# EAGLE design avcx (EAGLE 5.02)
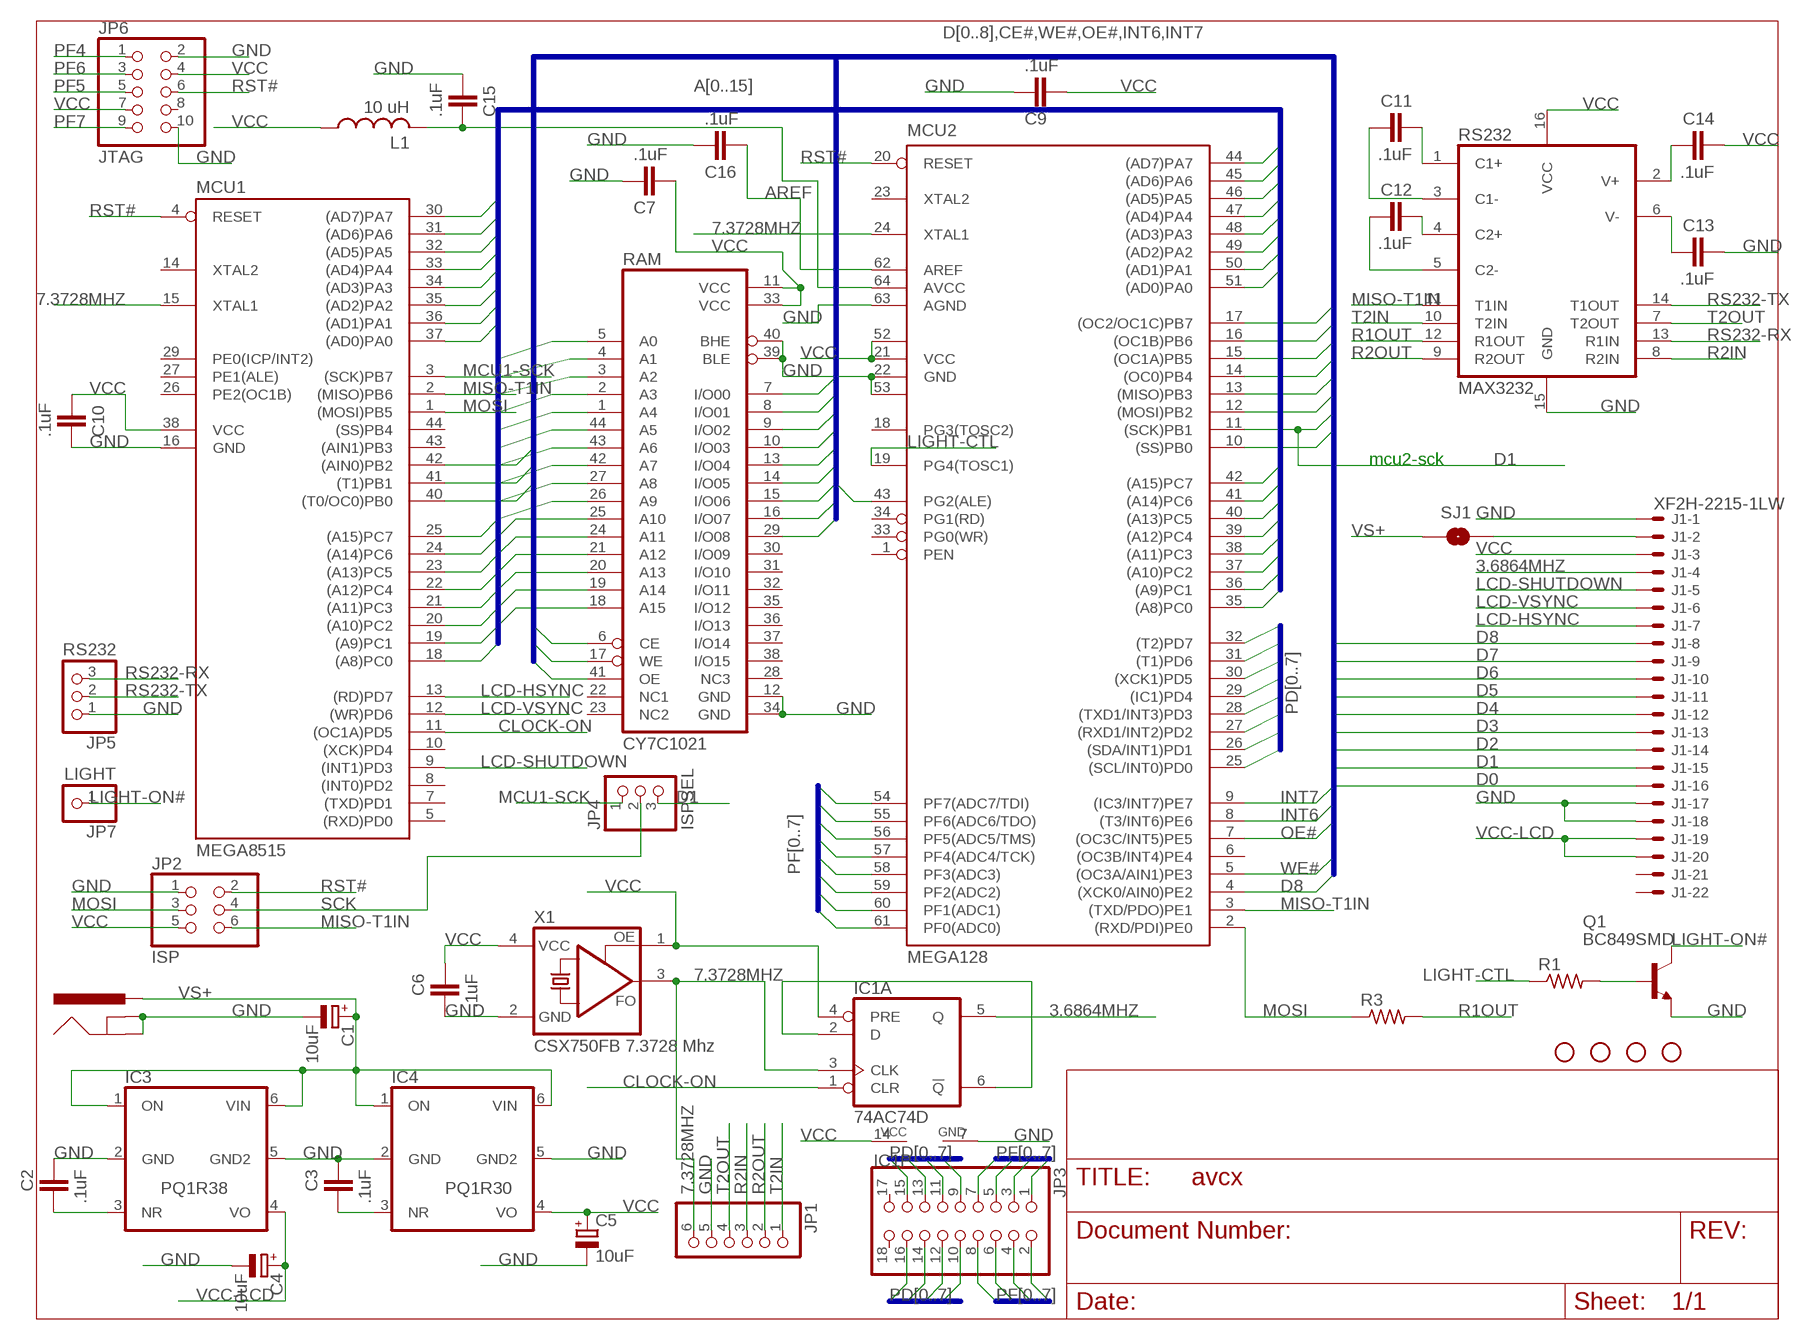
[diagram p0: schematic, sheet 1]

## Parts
C1  10uF  CPOL-EUCT3528  [CT3528]
C2  .1uF  C-EUC0603  [C0603]
C3  .1uF  C-EUC0603  [C0603]
C4  10uF  CPOL-EUCT3528  [CT3528]
C5  10uF  CPOL-EUCT3528  [CT3528]
C6  .1uF  C-EUC0603  [C0603]
C7  .1uF  C-EUC0603  [C0603]
C9  .1uF  C-EUC0603  [C0603]
C10  .1uF  C-EUC0603  [C0603]
C11  .1uF  C-EUC0603  [C0603]
C12  .1uF  C-EUC0603  [C0603]
C13  .1uF  C-EUC0603  [C0603]
C14  .1uF  C-EUC0603  [C0603]
C15  .1uF  C-EUC0603  [C0603]
C16  .1uF  C-EUC0603  [C0603]
IC1  74AC74D  [SO14]
IC3  PQ1R38  PQ1R  [SOT23-6L]
IC4  PQ1R30  PQ1R  [SOT23-6L]
J1  XF2H-2215-1LW  [XF2H-2215-1LW]
J2  POWER_JACKPTH  [POWER_JACK_PTH]
JP1  PINHD-1X6  [1X06]
JP2  ISP  PINHD-2X3  [2X03]
JP3  PINHD-2X9  [2X09]
JP4  ISPSEL  PINHD-1X3  [1X03]
JP5  RS232  PINHD-1X3  [1X03]
JP6  JTAG  PINHD-2X5  [2X05]
JP7  LIGHT  PINHD-1X1  [1X01]
L1  10 uH  L-USL2012C  [L2012C]
MCU1  MEGA8515  MEGA8515-A  [TQFP44]
MCU2  MEGA128  MEGA128-A  [TQFP64]
Q1  BC849SMD  [SOT23-BEC]
R1  R-US_R0603  [R0603]
R3  R-US_R0603  [R0603]
RAM  CY7C1021  CY7C1021CV33  [TSOPII-44]
RS232  MAX3232  MAX232SOIC16  [SO016]
SJ1  SOLDERJUMPERNO  [SJ-NO]
U$1  STAND-OFF  [STAND-OFF]
U$2  STAND-OFF  [STAND-OFF]
U$3  STAND-OFF  [STAND-OFF]
U$4  STAND-OFF  [STAND-OFF]
X1  CSX750FB 7.3728 Mhz  CSX750  [ASF]

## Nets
3.6864MHZ: IC1.5(A:Q) J1.4
7.3728MHZ: IC1.3(A:CLK) JP1.6 MCU1.15(XTAL1) MCU2.24(XTAL1) X1.3(FO)
A0: MCU1.37((AD0)PA0) MCU2.51((AD0)PA0) RAM.5(A0)
A1: MCU1.36((AD1)PA1) MCU2.50((AD1)PA1) RAM.4(A1)
A2: MCU1.35((AD2)PA2) MCU2.49((AD2)PA2) RAM.3(A2)
A3: MCU1.34((AD3)PA3) MCU2.48((AD3)PA3) RAM.2(A3)
A4: MCU1.33((AD4)PA4) MCU2.47((AD4)PA4) RAM.1(A4)
A5: MCU1.32((AD5)PA5) MCU2.46((AD5)PA5) RAM.44(A5)
A6: MCU1.31((AD6)PA6) MCU2.45((AD6)PA6) RAM.43(A6)
A7: MCU1.30((AD7)PA7) MCU2.44((AD7)PA7) RAM.42(A7)
A8: MCU1.18((A8)PC0) MCU2.35((A8)PC0) RAM.27(A8)
A9: MCU1.19((A9)PC1) MCU2.36((A9)PC1) RAM.26(A9)
A10: MCU1.20((A10)PC2) MCU2.37((A10)PC2) RAM.25(A10)
A11: MCU1.21((A11)PC3) MCU2.38((A11)PC3) RAM.24(A11)
A12: MCU1.22((A12)PC4) MCU2.39((A12)PC4) RAM.21(A12)
A13: MCU1.23((A13)PC5) MCU2.40((A13)PC5) RAM.20(A13)
A14: MCU1.24((A14)PC6) MCU2.41((A14)PC6) RAM.19(A14)
A15: MCU1.25((A15)PC7) MCU2.42((A15)PC7) RAM.18(A15)
AREF: C16.1 MCU2.62(AREF)
AVCC: C15.2 L1.2 MCU2.64(AVCC)
CE#: MCU2.43(PG2(ALE)) RAM.6(CE)
CLOCK-ON: IC1.1(A:CLR) MCU1.11((OC1A)PD5)
D0: J1.16 MCU2.10((SS)PB0) RAM.7(I/O00)
D1: J1.15 JP4.3 MCU2.11((SCK)PB1) RAM.8(I/O01)
D2: J1.14 MCU2.12((MOSI)PB2) RAM.9(I/O02)
D3: J1.13 MCU2.13((MISO)PB3) RAM.10(I/O03)
D4: J1.12 MCU2.14((OC0)PB4) RAM.13(I/O04)
D5: J1.11 MCU2.15((OC1A)PB5) RAM.14(I/O05)
D6: J1.10 MCU2.16((OC1B)PB6) RAM.15(I/O06)
D7: J1.9 MCU2.17((OC2/OC1C)PB7) RAM.16(I/O07)
D8: J1.8 MCU2.4((XCK0/AIN0)PE2) RAM.29(I/O08)
GND: C1.- C2.2 C3.2 C4.- C5.- C6.1 C7.2 C9.2 C10.2 C13.2 C15.1 C16.2 IC1.7(P:GND) IC3.2(GND) IC3.5(GND2) IC4.2(GND) IC4.5(GND2) J1.1 J1.17 J1.18 J2.GND J2.GNDBREAK JP1.5 JP2.1 JP5.1 JP6.2 JP6.10 MCU1.16(GND) MCU2.22(GND) MCU2.53(GND1) MCU2.63(AGND) Q1.E RAM.12(GND) RAM.34(GND) RAM.39(BLE) RAM.40(BHE) RS232.15(GND) X1.2(GND)
INT6: MCU1.42((AIN0)PB2) MCU2.8((T3/INT6)PE6)
INT7: MCU1.41((T1)PB1) MCU2.9((IC3/INT7)PE7)
LCD-HSYNC: J1.7 MCU1.13((RD)PD7)
LCD-SHUTDOWN: J1.5 MCU1.9((INT1)PD3)
LCD-VSYNC: J1.6 MCU1.12((WR)PD6)
LIGHT-CTL: MCU2.19(PG4(TOSC1)) R1.1
LIGHT-ON#: JP7.1 Q1.C
MCU1-SCK: JP4.1 MCU1.3((SCK)PB7)
MISO-T1IN: JP2.6 MCU1.2((MISO)PB6) MCU2.3((TXD/PDO)PE1) RS232.11(T1IN)
MOSI: JP2.3 MCU1.1((MOSI)PB5) MCU2.2((RXD/PDI)PE0) R3.1
N$1: C11.2 RS232.1(C1+)
N$2: C11.1 RS232.3(C1-)
N$3: C14.1 RS232.2(V+)
N$4: C12.2 RS232.4(C2+)
N$5: C12.1 RS232.5(C2-)
N$6: C13.1 RS232.6(V-)
N$7: IC1.2(A:D) IC1.6(A:!Q)
N$8: Q1.B R1.2
N$9: J1.2 SJ1.2
N$13: C2.1 IC3.3(NR)
N$14: C3.1 IC4.3(NR)
OE#: MCU1.40((T0/OC0)PB0) MCU2.7((OC3C/INT5)PE5) RAM.41(OE)
PD0: JP3.15 MCU2.25((SCL/INT0)PD0)
PD1: JP3.16 MCU2.26((SDA/INT1)PD1)
PD2: JP3.13 MCU2.27((RXD1/INT2)PD2)
PD3: JP3.14 MCU2.28((TXD1/INT3)PD3)
PD4: JP3.11 MCU2.29((IC1)PD4)
PD5: JP3.12 MCU2.30((XCK1)PD5)
PD6: JP3.9 MCU2.31((T1)PD6)
PD7: JP3.10 MCU2.32((T2)PD7)
PF0: JP3.2 MCU2.61(PF0(ADC0))
PF1: JP3.1 MCU2.60(PF1(ADC1))
PF2: JP3.4 MCU2.59(PF2(ADC2))
PF3: JP3.3 MCU2.58(PF3(ADC3))
PF4: JP3.6 JP6.1 MCU2.57(PF4(ADC4/TCK))
PF5: JP3.5 JP6.5 MCU2.56(PF5(ADC5/TMS))
PF6: JP3.8 JP6.3 MCU2.55(PF6(ADC6/TDO))
PF7: JP3.7 JP6.9 MCU2.54(PF7(ADC7/TDI))
R1OUT: R3.2 RS232.12(R1OUT)
R2IN: JP1.3 RS232.8(R2IN)
R2OUT: JP1.2 RS232.9(R2OUT)
RS232-RX: JP5.3 RS232.13(R1IN)
RS232-TX: JP5.2 RS232.14(T1OUT)
RST#: JP2.2 JP6.6 MCU1.4(RESET) MCU2.20(RESET)
SCK: JP2.4 JP4.2
T2IN: JP1.1 RS232.10(T2IN)
T2OUT: JP1.4 RS232.7(T2OUT)
VCC: C5.+ C6.2 C7.1 C9.1 C10.1 C14.2 IC1.4(A:PRE) IC1.14(P:VCC) IC4.4(VO) J1.3 JP2.5 JP6.4 JP6.7 L1.1 MCU1.38(VCC) MCU2.21(VCC) MCU2.52(VCC1) RAM.11(VCC) RAM.33(VCC) RS232.16(VCC) X1.1(OE) X1.4(VCC)
VCC-LCD: C4.+ IC3.4(VO) J1.19 J1.20
VS+: C1.+ IC3.1(ON) IC3.6(VIN) IC4.1(ON) IC4.6(VIN) J2.PWR SJ1.1
WE#: MCU2.5((OC3A/AIN1)PE3) RAM.17(WE)
Unconnected: IC1.8(B:!Q) IC1.9(B:Q) IC1.10(B:PRE) IC1.11(B:CLK) IC1.12(B:D) IC1.13(B:CLR) J1.21 J1.22 JP3.17 JP3.18 JP6.8 MCU1.5((RXD)PD0) MCU1.6(NC1) MCU1.7((TXD)PD1) MCU1.8((INT0)PD2) MCU1.10((XCK)PD4) MCU1.14(XTAL2) MCU1.17(NC2) MCU1.26(PE2(OC1B)) MCU1.27(PE1(ALE)) MCU1.28(NC3) MCU1.29(PE0(ICP/INT2)) MCU1.39(NC4) MCU1.43((AIN1)PB3) MCU1.44((SS)PB4) MCU2.1(PEN) MCU2.6((OC3B/INT4)PE4) MCU2.18(PG3(TOSC2)) MCU2.23(XTAL2) MCU2.33(PG0(WR)) MCU2.34(PG1(RD)) RAM.22(NC1) RAM.23(NC2) RAM.28(NC3) RAM.30(I/O09) RAM.31(I/O10) RAM.32(I/O11) RAM.35(I/O12) RAM.36(I/O13) RAM.37(I/O14) RAM.38(I/O15)

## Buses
A[0..15]
D[0..8],CE#,WE#,OE#,INT6,INT7
PD[0..7]
PF[0..7]

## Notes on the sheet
- mcu2-sck

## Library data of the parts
C1 C4 C5 = rcl:CPOL-EU: POLARIZED CAPACITOR, European symbol
C2 C3 C6 C7 C9-C16 = resistor:C-EU: CAPACITOR, European symbol
IC1 = 74xx-eu:74*74: Dual D type positive edge triggered FLIP FLOP, preset and clear
IC3 IC4 = Jdr-Eagle:PQ1R: Sharp Low Power Loss Low Voltage Regulator
J1 = con-omron:XF2*-22?: OMRON FPC Connector Source : http://www.omron.com/ecb/products/pdf/fpc.pdf
J2 = SparkFun:POWER_JACK: Power Jack This is the standard 5.5mm barrel jack for power. The PTH is the most common, proven, reliable, footprint. All others are experimental. The Slot footprint only works if the mill layer is transmitted to the PCB fab house so be warned. Spark Fun Electronics SKU : PRT-00119. Mating wall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
JP1 = pinhead:PINHD-1X6: PIN HEADER
JP2 = pinhead:PINHD-2X3: PIN HEADER
JP3 = pinhead:PINHD-2X9: PIN HEADER
JP4 JP5 = pinhead:PINHD-1X3: PIN HEADER
JP6 = pinhead:PINHD-2X5: PIN HEADER
JP7 = pinhead:PINHD-1X1: PIN HEADER
L1 = rcl:L-US: INDUCTOR, American symbol
MCU1 = atmel:MEGA8515: MICROCONTROLLER 8 Kbytes FLASH 512 bytes SRAM 512 bytes EEPROM USART 8-channel 10 bit ADC Source: avr.lbr
MCU2 = atmel:MEGA128: MICROCONTROLLER 128 Kbytes FLASH 4 Kbytes SRAM 4 Kbytes EEPROM DUAL USART 8-channel 10 bit ADC Source: avr.lbr
Q1 = transistor-npn:BC849*: NPN Transistor
R1 R3 = resistor:R-US_: RESISTOR, American symbol
RAM = Jdr-Eagle:CY7C1021CV33
RS232 = SparkFun:MAX232: RS232 Transceiver Very common IC. This is generically called 'MAX232', but works with the 3V equivalent MAX3232 generic ICs. Field tested and mother approved. Spark Fun Electronics SKU : COM-00316 (DIP) and COM-00589 (SMD)
SJ1 = SparkFun:SOLDERJUMPER: Solder Jumper
U$1-U$4 = SparkFun:STAND-OFF: Stand Off
X1 = Jdr-Eagle:CSX750

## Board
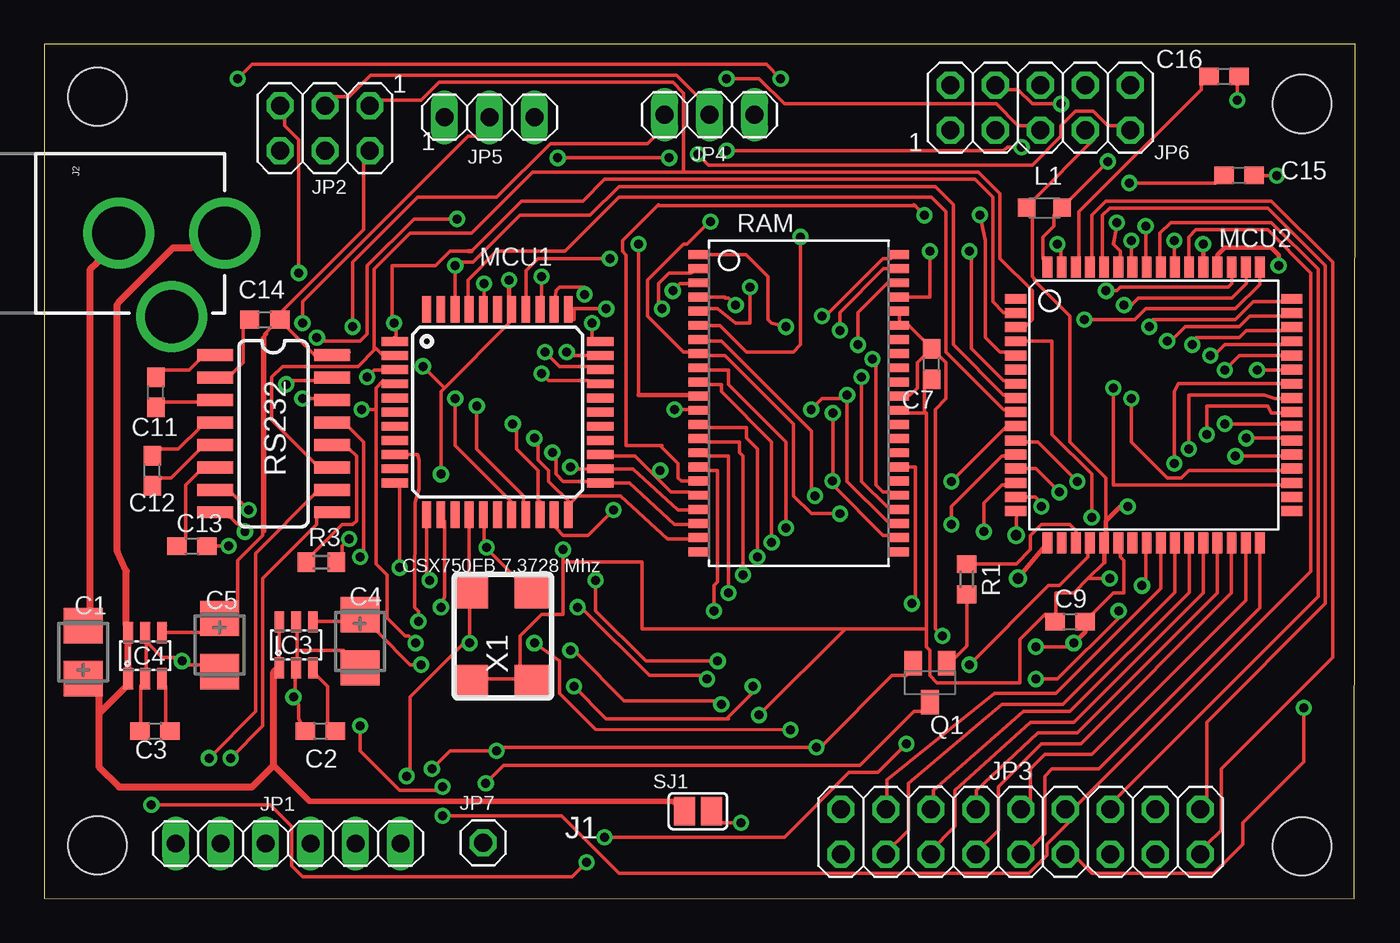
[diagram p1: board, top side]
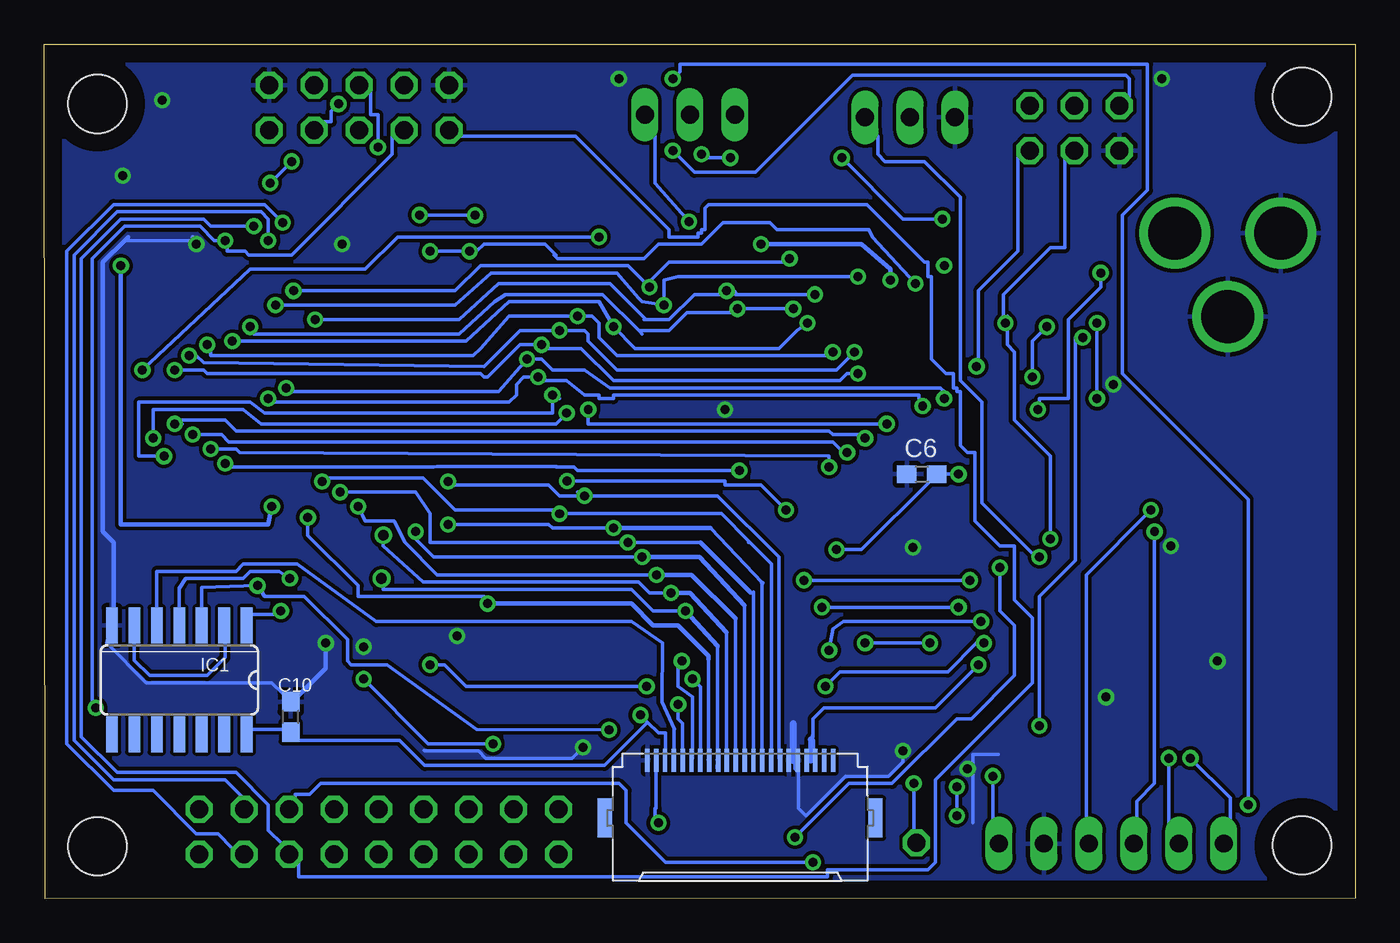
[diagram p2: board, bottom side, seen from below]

Size 74.09 x 48.3 mm. Coordinates in mm from the lower left corner, seen from the top.
Outline: 0,0.03 74.04,0 74.09,48.3 0,48.3 0,0.03
Copper layers (1*16): Top 0.035mm / dielectric 1.5mm / Bottom 0.035mm
Design rules "default *": minimum track width 8mil, minimum drill 20mil, track to track 8mil, track to pad 8mil, pad to pad 8mil, via to via 8mil, smd to smd 8mil, copper to edge 40mil, drill to drill 8mil, minimum pad ring 10mil, minimum via ring 8mil, stop-mask expansion 4mil, vias tented up to drill 0mil, thermal gap 10mil

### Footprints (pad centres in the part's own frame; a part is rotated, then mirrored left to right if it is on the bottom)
CT3528 = smd 2 x 2.2: + -1.5,0; - 1.5,0
C0603 = smd 1.1 x 1: 1 -0.85,0; 2 0.85,0
SO14 = smd 0.66 x 2.032: 1 -3.81,-3.073; 2 -2.54,-3.073; 3 -1.27,-3.073; 4 0,-3.073; 5 1.27,-3.073; 6 2.54,-3.073; 7 3.81,-3.073; 8 3.81,3.073; 9 2.54,3.073; 10 1.27,3.073; 11 0,3.073; 12 -1.27,3.073; 13 -2.54,3.073; 14 -3.81,3.073
SOT23-6L = smd 0.55 x 1.2: 1 -0.9,-1.3; 2 0.05,-1.3; 3 1,-1.3; 4 1,1.3; 5 0.05,1.3; 6 -0.9,1.3
XF2H-2215-1LW = smd 1.3 x 0.25: 1 3.175,5.25; 2 3.175,4.75; 3 3.175,4.25; 4 3.175,3.75; 5 3.175,3.25; 6 3.175,2.75; 7 3.175,2.25; 8 3.175,1.75; 9 3.175,1.25; 10 3.175,0.75; 11 3.175,0.25; 12 3.175,-0.25; 13 3.175,-0.75; 14 3.175,-1.25; 15 3.175,-1.75; 16 3.175,-2.25; 17 3.175,-2.75; 18 3.175,-3.25; 19 3.175,-3.75; 20 3.175,-4.25; 21 3.175,-4.75; 22 3.175,-5.25 | smd 2.2 x 0.8: M1 -0.075,7.65; M2 -0.075,-7.65
POWER_JACK_PTH = drill 2.997 round: GND 0,7.7; GNDBREAK 4.7,10.7; PWR 0,13.7
1X06 = drill 1.016 long: 1 -6.35,0; 2 -3.81,0; 3 -1.27,0; 4 1.27,0; 5 3.81,0; 6 6.35,0
2X03 = drill 1.016 octagon: 1 -2.54,-1.27; 2 -2.54,1.27; 3 0,-1.27; 4 0,1.27; 5 2.54,-1.27; 6 2.54,1.27
2X09 = drill 1.016 octagon: 1 -10.16,-1.27; 2 -10.16,1.27; 3 -7.62,-1.27; 4 -7.62,1.27; 5 -5.08,-1.27; 6 -5.08,1.27; 7 -2.54,-1.27; 8 -2.54,1.27; 9 0,-1.27; 10 0,1.27; 11 2.54,-1.27; 12 2.54,1.27; 13 5.08,-1.27; 14 5.08,1.27; 15 7.62,-1.27; 16 7.62,1.27; 17 10.16,-1.27; 18 10.16,1.27
1X03 = drill 1.016 long: 1 -2.54,0; 2 0,0; 3 2.54,0
2X05 = drill 1.016 octagon: 1 -5.08,-1.27; 2 -5.08,1.27; 3 -2.54,-1.27; 4 -2.54,1.27; 5 0,-1.27; 6 0,1.27; 7 2.54,-1.27; 8 2.54,1.27; 9 5.08,-1.27; 10 5.08,1.27
1X01 = drill 1.016 octagon: 1 0,0
L2012C = smd 1 x 1: 1 -1,0; 2 1,0
TQFP44 = smd 1.5 x 0.5: 1 -5.8,4; 2 -5.8,3.2; 3 -5.8,2.4; 4 -5.8,1.6; 5 -5.8,0.8; 6 -5.8,0; 7 -5.8,-0.8; 8 -5.8,-1.6; 9 -5.8,-2.4; 10 -5.8,-3.2; 11 -5.8,-4; 23 5.8,-4; 24 5.8,-3.2; 25 5.8,-2.4; 26 5.8,-1.6; 27 5.8,-0.8; 28 5.8,0; 29 5.8,0.8; 30 5.8,1.6; 31 5.8,2.4; 32 5.8,3.2; 33 5.8,4 | smd 0.5 x 1.5: 12 -4,-5.8; 13 -3.2,-5.8; 14 -2.4,-5.8; 15 -1.6,-5.8; 16 -0.8,-5.8; 17 0,-5.8; 18 0.8,-5.8; 19 1.6,-5.8; 20 2.4,-5.8; 21 3.2,-5.8; 22 4,-5.8; 34 4,5.8; 35 3.2,5.8; 36 2.4,5.8; 37 1.6,5.8; 38 0.8,5.8; 39 0,5.8; 40 -0.8,5.8; 41 -1.6,5.8; 42 -2.4,5.8; 43 -3.2,5.8; 44 -4,5.8
TQFP64 = smd 1.194 x 0.559: 1 -7.8,6; 2 -7.8,5.2; 3 -7.8,4.4; 4 -7.8,3.6; 5 -7.8,2.8; 6 -7.8,2; 7 -7.8,1.2; 8 -7.8,0.4; 9 -7.8,-0.4; 10 -7.8,-1.2; 11 -7.8,-2; 12 -7.8,-2.8; 13 -7.8,-3.6; 14 -7.8,-4.4; 15 -7.8,-5.2; 16 -7.8,-6; 33 7.8,-6; 34 7.8,-5.2; 35 7.8,-4.4; 36 7.8,-3.6; 37 7.8,-2.8; 38 7.8,-2; 39 7.8,-1.2; 40 7.8,-0.4; 41 7.8,0.4; 42 7.8,1.2; 43 7.8,2; 44 7.8,2.8; 45 7.8,3.6; 46 7.8,4.4; 47 7.8,5.2; 48 7.8,6 | smd 0.559 x 1.194: 17 -6,-7.8; 18 -5.2,-7.8; 19 -4.4,-7.8; 20 -3.6,-7.8; 21 -2.8,-7.8; 22 -2,-7.8; 23 -1.2,-7.8; 24 -0.4,-7.8; 25 0.4,-7.8; 26 1.2,-7.8; 27 2,-7.8; 28 2.8,-7.8; 29 3.6,-7.8; 30 4.4,-7.8; 31 5.2,-7.8; 32 6,-7.8; 49 6,7.8; 50 5.2,7.8; 51 4.4,7.8; 52 3.6,7.8; 53 2.8,7.8; 54 2,7.8; 55 1.2,7.8; 56 0.4,7.8; 57 -0.4,7.8; 58 -1.2,7.8; 59 -2,7.8; 60 -2.8,7.8; 61 -3.6,7.8; 62 -4.4,7.8; 63 -5.2,7.8; 64 -6,7.8
SOT23-BEC = smd 1 x 1.4: B -0.95,-1.1; C 0,1.1; E 0.95,-1.1
R0603 = smd 1 x 1.1: 1 -0.85,0; 2 0.85,0
TSOPII-44 = smd 0.5 x 1.2: 1 -8.4,-5.627; 2 -7.6,-5.627; 3 -6.8,-5.627; 4 -6,-5.627; 5 -5.2,-5.627; 6 -4.4,-5.627; 7 -3.6,-5.627; 8 -2.8,-5.627; 9 -2,-5.627; 10 -1.2,-5.627; 11 -0.4,-5.627; 12 0.4,-5.627; 13 1.2,-5.627; 14 2,-5.627; 15 2.8,-5.627; 16 3.6,-5.627; 17 4.4,-5.627; 18 5.2,-5.627; 19 6,-5.627; 20 6.8,-5.627; 21 7.6,-5.627; 22 8.4,-5.627; 23 8.4,5.627; 24 7.6,5.627; 25 6.8,5.627; 26 6,5.627; 27 5.2,5.627; 28 4.4,5.627; 29 3.6,5.627; 30 2.8,5.627; 31 2,5.627; 32 1.2,5.627; 33 0.4,5.627; 34 -0.4,5.627; 35 -1.2,5.627; 36 -2,5.627; 37 -2.8,5.627; 38 -3.6,5.627; 39 -4.4,5.627; 40 -5.2,5.627; 41 -6,5.627; 42 -6.8,5.627; 43 -7.6,5.627; 44 -8.4,5.627
SO016 = smd 0.66 x 2.032: 1 -4.445,-3.315; 2 -3.175,-3.315; 3 -1.905,-3.315; 4 -0.635,-3.315; 5 0.635,-3.315; 6 1.905,-3.315; 7 3.175,-3.315; 8 4.445,-3.315; 9 4.445,3.315; 10 3.175,3.315; 11 1.905,3.315; 12 0.635,3.315; 13 -0.635,3.315; 14 -1.905,3.315; 15 -3.175,3.315; 16 -4.445,3.315
SJ-NO = smd 1.168 x 1.6: 1 -0.762,0; 2 0.762,0
STAND-OFF = hole 3.302: 0,0
ASF = smd 1.8 x 2: 1 1.21,1.34; 2 6.21,1.34; 3 6.21,4.84; 4 1.21,4.84

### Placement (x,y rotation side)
C1  2.2,13.94 90 top
C2  15.61,9.47 180 top
C3  6.26,9.47 180 top
C4  17.84,14.55 270 top
C5  9.92,14.35 270 top
C6  24.5,24 0 bottom
C7  50.15,30.22 90 top
C9  57.98,15.67 0 top
C10  60.16,10.28 90 bottom
C11  6.31,28.62 90 top
C12  6.11,24.2 90 top
C13  8.34,19.93 0 top
C14  12.46,32.74 0 top
C15  67.53,40.89 180 top
C16  66.69,46.48 0 top
IC1  66.46,12.36 180 bottom
IC3  14.19,14.35 0 top
IC4  5.65,13.74 0 top
J1  34.76,4.64 90 bottom
J2  -3.49,37.61 270 top
JP1  13.78,3.12 0 top
JP2  15.86,43.56 0 top
JP3  55.18,3.78 180 top
JP4  37.6,44.32 0 top
JP5  25.16,44.17 0 top
JP6  56.3,44.72 0 top
JP7  24.8,3.17 0 top
L1  56.53,39.06 0 top
MCU1  25.62,27.5 0 top
MCU2  62.7,27.91 0 top
Q1  50.05,12.21 180 top
R1  52.13,18.05 270 top
R3  15.66,19.02 180 top
RAM  42.63,28.01 270 top
RS232  12.97,26.28 270 top
SJ1  36.94,4.95 0 top
U$1  3.01,3.02 0 top
U$2  71.08,2.97 0 top
U$3  3.01,45.33 0 top
U$4  71.08,44.93 0 top
X1  28.92,11.09 90 top

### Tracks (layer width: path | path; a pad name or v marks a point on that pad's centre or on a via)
3.6864MHZ
  Bottom 0.203: J1.4 38.51,9.57 | 38.51,9.57 38.51,9.61 | IC1.5 67.73,18.51 63.26,18.51 62.85,18.92 59.8,18.92 55.33,15.67 40.91,15.67 39.15,14.45 39.18,11.12 38.47,9.57 38.51,9.57
7.3728MHZ  (via drill 0.51)
  Top 0.203: MCU1.15 24.02,17.11 24.04,17.09 | v27.7,14.45 29.12,13.43 29.12,11.6 31.15,9.57 v42.18,9.55 | 24.04,17.09 24.08,17.13 X1.3 | 24.04,17.09 v24.04,14.45 23.74,14.45 20.69,11.4 20.69,7.34 v20.48,6.93 | MCU2.24 62.27,20.11 62.24,20.14 62.24,17.9 v62.04,17.7
  Bottom 0.203: v42.18,9.55 49.64,9.57 54.72,13.23 56.76,13.23 56.96,13.43 56.96,14.65 59.4,17.09 61.63,17.09 v62.04,17.7 65.19,17.6 IC1.3 | v24.04,14.45 v27.7,14.45 | v20.48,6.93 20.48,4.49 JP1.6
A0  (via drill 0.51)
  Top 0.203: MCU2.51 67.12,34.77 66.92,34.56 60.82,34.56 60.62,34.36 v60.01,34.36 | 37.05,33.35 38.06,33.35 39.08,32.53 39.89,32.53 v39.89,34.56 | MCU1.37 27.22,35.5 27.9,36.19 v31.97,36.19
  Top 0.229: 37.05,33.35 RAM.5
  Bottom 0.203: v60.01,34.36 50.86,34.36 49.44,35.78 41.11,35.78 v39.89,34.56 39.79,34.97 38.77,35.99 32.27,35.99 v31.97,36.19
A1  (via drill 0.51)
  Top 0.203: MCU2.50 67.93,34.77 67.12,33.96 61.84,33.96 61.43,33.55 v61.02,33.55 | MCU1.36 28.11,33.39 v28.11,35.17 | RAM.4 38.47,34.01 38.47,33.96 38.67,33.96 v39.08,33.55
  Bottom 0.203: v61.02,33.55 50.86,33.55 48.83,35.38 41.72,35.38 40.5,33.96 40.3,33.75 v39.08,33.55 39.08,34.97 38.27,35.17 v28.11,35.17
A2  (via drill 0.51)
  Top 0.203: MCU2.49 68.7,34.72 67.32,33.35 62.24,33.35 61.63,32.74 v58.79,32.74 | MCU1.35 28.92,34.36 29.12,34.56 30.54,34.56 v30.54,34.16 | v35.52,34.36 35.93,34.77 36.54,34.77 RAM.3
  Bottom 0.203: 40.15,32.79 40.09,32.74 | 40.15,32.79 42.13,34.77 48.43,34.77 50.66,32.74 v58.79,32.74 | v30.54,34.16 34.91,34.16 | 34.91,34.16 35.01,34.16 | 34.91,34.16 35.12,34.36 v35.52,34.36 35.93,34.16 37.35,34.16 38.77,32.74 40.2,32.74 40.15,32.79
A3  (via drill 0.51)
  Top 0.203: MCU1.34 29.53,32.74 29.93,32.74 29.93,33.35 v31.76,33.35 | MCU2.48 69.96,33.75 68.34,33.75 67.32,32.74 62.65,32.74 v62.45,32.33 | v34.91,33.35 34.71,33.55 34.71,34.77 35.32,35.38 36.54,35.38 RAM.2
  Bottom 0.203: v62.45,32.33 62.24,31.92 50.66,31.92 48.63,33.75 48.02,34.16 42.53,34.16 40.45,32.08 | 40.45,32.08 40.3,31.92 | 31.76,32.94 v31.76,33.35 v34.91,33.35 35.32,33.14 37.76,33.14 38.77,32.13 40.4,32.13 40.45,32.08
A4  (via drill 0.51)
  Top 0.203: RAM.1 39.67,36.41 40.91,35.17 40.91,32.74 41.11,32.53 v41.92,32.33 | 70.17,33.14 70.2,33.11 MCU2.47 69.96,32.94 68.14,32.94 67.53,32.33 64.48,32.33 63.87,31.72 v63.46,31.52 | MCU1.33 30.96,31.5 30.95,31.52 v30.95,32.53
  Bottom 0.203: v63.46,31.52 50.25,31.52 47.82,33.75 42.74,33.75 v41.92,32.33 40.7,31.11 32.58,31.11 31.56,32.13 v30.95,32.53
A5  (via drill 0.51)
  Top 0.203: 70.37,32.33 70.39,32.31 MCU2.46 69.96,32.13 67.93,32.13 67.53,31.72 65.09,31.72 v64.88,31.31 | v29.53,30.91 29.73,30.7 30.95,30.7 | 30.95,30.7 | 30.95,30.7 MCU1.32 | RAM.44 47.82,36.19 47.41,36.19 44.36,33.14 v43.96,32.94
  Bottom 0.203: v64.88,31.31 64.68,31.11 64.68,30.7 49.85,30.7 49.44,31.11 47.82,32.94 v43.96,32.94 43.14,32.94 42.74,32.53 42.74,31.72 41.72,30.7 29.73,30.7 v29.53,30.91
A6  (via drill 0.51)
  Top 0.203: RAM.43 47.44,35.61 44.97,33.14 v44.97,32.13 | 70.37,31.52 70.38,31.51 MCU2.45 69.96,31.31 66.71,31.31 66.31,30.91 v65.9,30.7 | 31.36,29.89 31.37,29.9 MCU1.31 30.75,30.09 29.12,30.09 v28.31,30.91
  Bottom 0.203: v65.9,30.7 65.49,30.7 65.09,30.3 49.24,30.09 47.21,32.13 v44.97,32.13 43.55,32.13 43.35,31.92 43.35,31.52 41.72,29.89 29.32,29.89 v28.31,30.91
A7  (via drill 0.51)
  Top 0.203: v66.71,29.89 67.53,30.7 69.96,30.7 MCU2.44 | v45.99,31.31 45.99,33.14 47.82,34.97 RAM.42 | v28.11,29.69 28.51,29.28 30.75,29.28 MCU1.30
  Bottom 0.203: v66.71,29.89 65.09,29.89 64.88,29.69 49.44,29.69 49.24,29.48 49.04,29.48 47.21,31.31 v45.99,31.31 45.58,31.11 43.75,31.11 41.92,29.28 29.12,29.28 28.71,29.69 v28.11,29.69
A8  (via drill 0.51)
  Top 0.203: 47,30.3 v46.8,30.5 47,30.09 47,23.39 47.41,22.98 47.82,22.98 RAM.27 | v23.23,28.27 23.23,25.62 26.48,22.37 MCU1.18 | v60.41,28.88 60.41,23.39 69.96,23.39 MCU2.35
  Bottom 0.203: v23.23,28.27 23.23,28.67 23.43,28.88 42.13,28.88 43.55,29.89 45.38,29.89 45.99,30.5 v46.8,30.5 48.43,28.67 60.21,28.67 v60.41,28.88
A9  (via drill 0.51)
  Top 0.203: 48.26,21.97 RAM.26 47.82,22.17 47.61,22.17 46.19,23.59 v46.19,29.48 | v24.45,27.86 24.45,25.42 27.09,22.78 27.09,22.37 MCU1.19 | v61.43,28.27 61.43,25.83 63.46,23.8 64.28,23.8 64.68,24.2 69.96,24.2 MCU2.36
  Bottom 0.203: v24.45,27.86 24.65,28.27 24.65,28.47 41.92,28.47 41.92,28.27 42.74,28.27 42.74,28.47 43.55,28.47 44.56,29.28 45.78,29.28 v46.19,29.48 47,29.48 47.41,29.08 47.41,28.47 47.82,28.06 61.23,28.06 v61.43,28.27
A10  (via drill 0.51)
  Top 0.203: 28.02,22.46 MCU1.20 27.9,22.37 27.9,24.2 26.68,25.42 26.68,26.44 v26.48,26.84 | RAM.25 47.82,21.36 47.61,21.36 45.38,23.59 v45.38,28.47 44.97,28.27 43.96,28.27 v43.35,27.66 | v67.32,25.01 69.96,25.01 MCU2.37
  Bottom 0.203: 44.97,28.27 v45.38,28.47 45.38,27.45 61.63,27.45 62.45,28.06 68.75,28.06 68.75,25.01 v67.32,25.01 | v43.35,27.66 43.35,26.84 v26.48,26.84
A11  (via drill 0.51)
  Top 0.203: v32.17,21.97 30.75,20.54 29.32,20.54 28.92,20.95 28.92,21.15 MCU1.21 | RAM.24 47.82,20.54 47.41,20.54 44.56,23.39 v44.54,23.62 44.56,24 v44.56,27.45 | v67.93,26.03 69.96,26.03 MCU2.38
  Bottom 0.203: v44.56,27.45 45.17,26.84 61.84,26.84 62.85,27.66 67.93,27.66 v67.93,26.03 | v32.17,21.97 33.59,23.39 35.62,23.39 35.62,23.62 v44.54,23.62
A12  (via drill 0.51)
  Top 0.203: 70.43,26.64 MCU2.39 69.96,26.84 v66.71,26.84 | RAM.21 36.94,20.34 35.22,20.34 32.58,22.78 30.14,22.78 29.73,22.37 | 29.73,22.37 28.51,23.59 28.51,24.2 27.9,24.81 27.9,25.62 v27.7,26.03 | MCU1.22 29.73,22.37
  Bottom 0.203: v27.7,26.03 28.11,26.23 29.53,26.23 29.73,26.44 63.26,26.44 63.87,27.05 66.31,27.05 v66.71,26.84 66.31,26.84
A13  (via drill 0.51)
  Top 0.203: MCU2.40 70.44,27.45 69.36,27.45 69.15,27.86 65.7,27.86 v65.7,26.23 | RAM.20 37.01,21.19 37.05,21.15 35.62,21.15 33.07,23.5 MCU1.23 30.75,23.59 29.32,23.59 28.92,24 28.92,24.81 v28.71,25.22
  Bottom 0.203: v28.71,25.22 29.12,25.42 29.53,25.83 63.67,25.83 64.07,26.23 v65.7,26.23
A14  (via drill 0.51)
  Top 0.203: v64.68,25.42 64.68,28.47 68.95,28.47 69.56,28.27 70.46,28.27 MCU2.41 | v29.73,24.4 29.83,24.3 MCU1.24 33.29,24.3 35.83,21.97 36.84,21.97 36.89,22.01 RAM.19
  Top 0.254: v64.68,25.42 64.68,25.67
  Bottom 0.203: v29.73,24.4 29.73,25.01 63.06,25.22 63.26,25.42 v64.68,25.42
A15  (via drill 0.51)
  Top 0.203: MCU2.42 64.1,29.11 63.87,28.67 v63.87,24.61 | 34.4,24 33.39,25.01 31.97,25.01 MCU1.25 | 34.4,24 35.42,22.98 36.44,22.98 RAM.18 | 34.4,24 34.61,24 v34.81,24.2
  Bottom 0.203: 45.17,24.43 45.15,24.43 | 45.17,24.43 51.88,24.43 52.08,24.4 63.46,24.4 v63.87,24.61 | v34.81,24.2 43.96,24.2 44.16,24.4 45.17,24.4 45.17,24.43
AREF
  Top 0.203: C16.1 65.39,46.15 65.39,45.74 58.48,38.83 58.48,36.19 MCU2.62
AVCC  (via drill 0.51)
  Top 0.203: 56.76,36.19 MCU2.64 56.45,36.19 56.45,37.41 57.06,38.02 57.06,38.63 L1.2 57.87,39.44 v60.11,41.68 | v61.33,40.46 66.2,40.46 C15.2
  Bottom 0.203: v60.11,41.68 v61.33,40.46
CE#  (via drill 0.51)
  Top 0.203: RAM.6 38.18,32.41 39.69,30.91 42.33,30.91 42.74,31.31 v42.74,37.41 | MCU2.43 70.39,29.91 70.37,29.89 v68.54,29.89
  Bottom 0.203: v42.74,37.41 54.12,37.41 55.94,35.58 62.45,35.58 v68.54,29.89
CLOCK-ON  (via drill 0.51)
  Top 0.203: v20.08,18.72 20.08,23.39 MCU1.11 | v31.66,3.48 41.82,3.48 45.48,7.13 47.1,7.13 v48.73,8.76 | v56.05,12.42 57.26,12.42 60.72,15.87 v60.72,16.28
  Bottom 0.203: v20.08,18.72 20.08,16.28 19.27,15.46 19.27,12.62 21.7,10.18 22.52,10.18 26.18,6.52 28.61,6.52 v31.66,3.48 | v48.73,8.76 52.39,8.76 v56.05,12.42 | v60.72,16.28 60.92,16.07 62.34,16.07 IC1.1
D0  (via drill 0.51)
  Top 0.203: RAM.7 37.45,31.52 38.27,31.52 43.35,26.44 43.35,23.19 v43.55,22.78 | v51.27,23.59 54.32,26.64 MCU2.10
  Bottom 0.203: v43.55,22.78 36.03,22.78 32.58,19.32 32.58,7.95 J1.16 | v43.55,22.78 43.96,22.98 | v51.27,23.59 50.86,23.39 45.58,23.39 44.97,22.78 v43.55,22.78
D1  (via drill 0.51)
  Top 0.203: v58.38,23.59 56.15,25.83 55.33,25.83 MCU2.11 | v44.97,21.76 43.35,21.76 42.33,22.78 42.33,26.84 38.47,30.7 37.45,30.7 RAM.8 36.54,30.91 36.13,30.91 34.1,32.94 34.1,34.97 36.13,37 36.34,37 37.35,38.02 v37.66,38.27
  Top 0.254: 36.79,30.81 36.8,30.81 RAM.8
  Bottom 0.203: J1.15 32.98,8.35 32.98,18.92 34.25,20.19 | 34.25,20.19 35.83,21.76 v44.97,21.76 45.38,21.97 50.86,21.97 52.69,23.8 57.98,23.8 v58.38,23.59 | 34.25,20.19 34.3,20.14 | v37.66,38.27 39.59,40.46 39.59,43.1 JP4.3
D2  (via drill 0.51)
  Top 0.203: RAM.9 37.45,29.89 38.67,29.89 38.67,29.08 41.92,25.83 v41.92,20.95 | v51.27,21.15 51.27,22.17 54.12,25.01 54.32,25.01 MCU2.12
  Bottom 0.203: 33.49,17.85 36.44,20.95 | 33.54,7.82 33.54,17.85 | v51.27,21.15 45.58,21.15 45.38,20.95 v41.92,20.95
  Bottom 0.254: 36.44,20.95 v41.92,20.95 | 33.54,17.85 33.49,17.85 | J1.14 33.54,7.82
D3  (via drill 0.51)
  Top 0.203: MCU2.13 56.04,24.31 v57.37,22.98 | RAM.10 37.45,29.08 38.27,29.08 38.27,28.67 41.11,25.83 v41.11,20.14
  Bottom 0.203: J1.13 34.01,17.29 | 34.01,17.29 34.01,17.33 | v57.37,22.98 53.1,22.98 52.29,21.76 52.29,20.14 v41.11,20.14 37,20.14 | 34.01,17.29 34.2,17.29 34.2,17.34 | 34.01,17.29 34,17.29
  Bottom 0.254: 34.2,17.34 37,20.14
D4  (via drill 0.51)
  Top 0.203: RAM.13 37.45,26.64 39.69,26.64 39.69,26.03 40.3,25.42 v40.3,19.32 | v53.1,20.75 53.1,22.37 54.12,23.39 54.32,23.39 MCU2.14
  Bottom 0.203: J1.12 34.51,16.58 | v53.1,20.75 53.1,20.34 52.08,19.32 v40.3,19.32
  Bottom 0.254: 34.51,16.58 37.05,19.32 v40.3,19.32 | J1.12
D5  (via drill 0.51)
  Top 0.203: MCU2.15 56.01,22.71 56.35,22.37 v56.35,22.17 | RAM.14 37.45,25.83 39.28,25.83 39.28,25.22 39.48,25.01 v39.48,18.31
  Bottom 0.203: v39.48,18.31 51.88,18.31 53.71,20.14 54.32,21.36 55.94,21.36 v56.35,22.17 | J1.11 35.01,15.82
  Bottom 0.229: 35.01,7.34 J1.11 | 35.04,15.84 35.01,15.87
  Bottom 0.254: 35.01,15.82 35.04,15.84 37.5,18.31 v39.48,18.31 | J1.11
D6  (via drill 0.51, 0.6 pad 0.25)
  Top 0.203: v54.93,20.54 54.93,21.97 MCU2.16 | RAM.15 37.45,25.01 38.67,25.01 v38.67,17.29
  Bottom 0.203: 35.52,7.83 35.52,15.06 | v38.67,17.29 39.89,17.29 40.5,17.9 52.69,17.9 54.93,19.93 v54.93,20.54
  Bottom 0.254: 35.52,15.06 37.61,17.29 v38.67,17.29 | J1.10 35.52,7.83
D7  (via drill 0.51, 0.6 pad 0.25)
  Top 0.203: RAM.16 37.45,24.2 38.06,24.2 38.06,17.9 37.86,17.7 v37.86,16.28
  Top 0.254: v55.03,18.11 MCU2.17
  Bottom 0.203: v37.86,16.28 39.69,16.28 40.91,17.5 54.93,17.5 54.93,17.9 v55.03,18.11 | 36.03,7.84 36.03,14.24
  Bottom 0.229: 36.03,7.34 J1.9 | 36.03,14.24 36.03,14.3
  Bottom 0.254: 36.03,14.3 v37.86,16.28 | J1.9 36.03,7.84
D8  (via drill 0.51)
  Top 0.203: MCU2.4 56.95,31.51 56.96,31.52 56.96,26.23 59.2,24 v59.2,21.56 | RAM.29 48.83,24.4 49.24,24.4 49.24,16.68 v49.04,16.68
  Bottom 0.203: 36.54,7.85 36.54,13.53 | v59.2,21.56 59.2,20.54 56.35,17.7 56.35,17.09 49.24,17.09 v49.04,16.68
  Bottom 0.254: J1.8 36.54,7.85 | 36.54,13.53 36.54,13.74 38.27,15.46 39.69,15.46 40.91,16.68 v49.04,16.68
GND  (via drill 0.51)
  Top 0.203: C9.2 59.2,16.07 60.41,17.29 61.02,17.29 61.02,19.12 60.82,19.32 60.82,19.53 MCU2.22 | X1.2 26.68,18.11 25.06,19.73 25.06,19.93 v25.01,19.86 24.85,20.34 24.85,21.15 MCU1.16 | 14.29,14.04 14.29,15.06 IC3.5 | 14.29,14.04 14.29,13.64 IC3.2 | 14.29,14.04 16.93,14.04 C4.- 17.03,12.21 | 9.61,13.43 C5.- 8.9,13.23 8.09,13.23 v7.79,13.43 7.48,13.64 6.67,13.64 5.85,14.45 IC4.5 5.75,14.45 5.75,13.03 IC4.2 5.45,12.01 5.45,9.77 C3.2 | v35.62,27.66 36.44,27.66 RAM.12 | 2.3,16.28 C1.- 2.6,16.28 | C13.2 v10.43,19.93 | v13.68,29.08 13.88,29.28 15.3,29.28 RS232.15 | C2.2 14.39,10.18 14.39,10.99 v14.08,11.4 14.19,11.81 14.19,12.62 IC3.2 | IC3.2 14.39,12.62 | v50.76,14.85 50.36,15.26 50.36,27.66 50.97,28.27 50.97,30.3 50.56,30.7 C7.2 | 48.73,28.27 RAM.34 48.73,28.47 48.93,28.47 49.34,28.88 49.34,30.3 49.75,30.7 C7.2 | 48.73,13.43 Q1.E 48.73,12.62 47.92,12.62 44.06,8.76 v43.65,8.56 | v56.05,14.24 57.87,14.24 v58.18,14.45 | v69.66,40.86 68.85,40.86 C15.1 | v67.42,45.13 67.42,46.15 C16.2 | v57.26,37 57.47,36.8 57.47,36.19 MCU2.63 | v41.62,46.35 40.81,47.16 11.75,47.16 v10.94,46.35 | v21.91,7.34 22.92,8.35 v25.57,8.35 25.97,8.56 v43.65,8.56 | v43.65,8.56 43.68,8.56 | C7.2 49.75,31.52 48.73,32.53 RAM.39 48.32,32.53 48.32,33.14 RAM.40
  Top 0.254: MCU2.53 v65.5,37 v65.49,37 | C9.2 58.83,15.09 v58.18,14.45
  Top 0.406: 2.6,16.28 2.6,35.58 3.01,35.99 J2.GND
  Bottom 0.203: C10.2 60.62,11.6 61.23,12.21 68.34,12.21 70.57,14.45 IC1.7 | 21.6,4.29 21.6,8.15 20.18,8.15 | 69.56,37.21 65.9,37.21 v65.49,37 | J1.17 31.97,8.35 | v25.57,8.35 25.57,7.74 26.38,6.93 28.82,6.93 31.05,4.69 31.46,5.1 31.46,7.13 31.66,7.34 31.66,7.82 | v43.65,8.56 44.26,7.95 49.14,7.95 49.54,8.35 52.59,8.35 52.62,8.38
  Bottom 0.254: v65.49,37 65.49,37.21 65.7,37.41 | 69.36,37.41 69.56,37.21 70.78,35.99 70.78,20.75 70.17,20.14 70.17,15.46 | IC1.7 70.19,15.44 | C10.2 60.07,11.13 58.18,13.03 v58.18,14.45 | J1.18 31.66,7.82 31.76,7.82
  Bottom 0.406: 31.76,7.82 31.76,9.9
  pour Bottom: 0.37,48.03 73.8,48.03 73.72,0.3 0.29,0.3
INT6  (via drill 0.51)
  Top 0.203: MCU1.42 23.22,35.77 v23.23,35.78 23.63,35.99 24.24,35.99 26.89,38.63 29.63,38.63 | 54.93,28.27 54.9,28.29 MCU2.8 54.42,28.47 54.22,28.47 51.37,31.31 51.37,39.24 50.36,40.25 32.47,40.25 30.85,38.63 29.63,38.63 | 29.63,38.63 29.73,38.63
  Bottom 0.203: v23.23,35.78 23.43,35.78
INT7
  Top 0.203: MCU1.41 23.94,33.96 23.94,34.97 25.57,36.6 29.43,36.6 32.47,39.64 50.15,39.64 50.97,38.83 50.97,30.91 54.22,27.66 54.42,27.66 MCU2.9
LCD-HSYNC  (via drill 0.51)
  Top 0.203: v22.42,16.48 22.62,17.09 22.62,21.36 22.42,21.56 MCU1.13 | v37.45,12.42 37.05,12.62 34.2,12.62 30.54,16.28 v30.14,16.48
  Bottom 0.203: J1.7 37.01,11.97 v37.45,12.42 | v22.42,16.48 v30.14,16.48
LCD-SHUTDOWN  (via drill 0.51)
  Top 0.203: MCU1.9 21.11,25.1 21.2,24.81 21.2,23.19 20.97,22.4 20.92,16.48 21.15,16.25 v21.15,15.67 | v38.27,10.99 37.86,11.2 32.78,11.2 30.14,13.84 v29.73,14.04
  Bottom 0.203: v29.73,14.04 29.53,15.26 28.92,15.67 v21.15,15.67 | v38.27,10.99 38.27,10.18 38.01,9.93 J1.5
LCD-VSYNC  (via drill 0.51)
  Top 0.203: v38.06,13.43 35.01,13.43 34,13.44 34,13.43 31.15,16.28 v31.15,18 | MCU1.12 21.6,21.15 21.6,18.31 v21.78,18
  Bottom 0.203: v21.78,18 v31.15,18 | J1.6 37.51,8 37.45,7.95 37.45,11.4 38.27,12.01 38.27,13.43 v38.06,13.43
LIGHT-CTL
  Top 0.203: MCU2.19 58.3,20.83 57.98,21.15 56.35,21.15 55.74,20.54 55.74,19.73 54.93,18.92 52.29,18.92 52.27,18.9 R1.1
LIGHT-ON#  (via drill 0.51)
  Top 0.203: v24.96,6.52 25.97,7.54 46.09,7.54 49.14,10.59 49.75,10.59 Q1.C
  Bottom 0.203: v24.96,6.52 24.96,3.88 JP7.1
MCU1-SCK  (via drill 0.51)
  Top 0.203: v18.25,29.48 18.66,29.89 19.27,29.89 MCU1.3 | v17.44,32.33 17.44,35.99 21.09,39.64 25.57,39.64 28.61,42.69 34.1,42.69 34.51,43.1 JP4.1
  Bottom 0.203: v18.25,29.48 18.25,31.52 v17.44,32.33
MISO-T1IN
  Top 0.203: 20.89,37.61 20.79,37.61 | MCU1.2 19.16,30.7 18.76,31.11 18.71,31.06 | 18.71,31.06 17.74,30.09 13.47,30.09 12.87,29.48 12.87,27.05 15.3,24.61 RS232.11 | 20.89,37.61 20.69,37.61 18.66,35.58 18.66,31.11 18.71,31.06 | 20.89,37.61 24.14,37.61 27.6,41.07 36.13,41.07 | MCU2.3 55.44,32.33 55.84,32.74 55.84,34.36 54.01,36.19 54.01,39.85 52.79,41.07 36.13,41.07 | 36.13,41.07 36.13,45.54 35.52,46.15 22.31,46.15 21.3,45.13 19.06,45.13 JP2.6
MOSI  (via drill 0.51)
  Top 0.203: 19.77,31.72 MCU1.1 19.88,31.72 19.88,32.13 v19.77,32.53 19.67,32.94 19.67,35.78 22.11,35.78 22.92,36.6 23.94,36.6 | v17.23,20.34 16.83,19.93 16.83,19.53 R3.1 | 24.14,36.6 26.99,39.44 30.44,39.44 31.66,40.66 52.59,40.66 53.61,39.64 53.61,33.75 54.22,33.14 54.42,33.14 MCU2.2
  Top 0.254: 23.94,36.6 24.14,36.6
  Bottom 0.203: v17.23,20.34 17.23,25.01 19.27,27.05 19.27,30.91 19.67,31.31 19.67,32.13 v19.77,32.53 | v19.77,32.53 19.67,32.94 | JP2.3 16.42,41.88 16.42,36.8 17.23,36.8 19.88,34.16 19.88,32.94 v19.77,32.53
N$1
  Top 0.203: C11.2 6.77,29.89 8.19,29.89 8.8,30.5 RS232.1
N$2
  Top 0.203: C11.1 6.77,28.06 8.8,28.06 RS232.3
N$3
  Top 0.203: C14.1 11.24,32.33 11.24,30.3 10.63,29.69 RS232.2
N$4
  Top 0.203: C12.2 6.57,25.42 7.58,25.42 8.8,26.64 RS232.4
N$5
  Top 0.203: C12.1 6.57,23.8 7.18,23.8 8.8,25.42 RS232.5
N$6
  Top 0.203: C13.1 7.99,20.34 7.99,23.39 8.8,24.2 RS232.6
N$7
  Bottom 0.203: IC1.6 69,13.48 68.14,12.62 64.88,12.62 63.87,13.64 63.87,15.46 63.89,15.44 IC1.2
N$8
  Top 0.203: Q1.B 51,13.29 51.07,13.23 52.13,14.3 R1.2
N$9  (via drill 0.51)
  Top 0.203: v39.38,4.29 38.16,4.29 SJ1.2
  Bottom 0.203: v39.38,4.29 39.59,4.69 39.59,5.1 39.51,5.1 J1.2 | J1.2
N$13
  Top 0.203: 15.2,12.62 IC3.3 15.4,12.62 16.02,12.01 16.02,9.77 C2.1
N$14
  Top 0.203: C3.1 6.87,9.77 6.87,12.01 IC4.3
OE#  (via drill 0.51)
  Top 0.203: 54.93,29.08 54.93,29.11 MCU2.7 54.42,29.28 54.22,29.28 52.39,31.11 52.39,36.19 v52.29,36.6 | RAM.41 50.05,34.01 v50.05,36.6 | MCU1.40 24.85,33.35 v24.85,34.77
  Bottom 0.203: v52.29,36.6 v50.05,36.6 49.64,36.6 49.24,37 45.78,37 45.23,36.44 | 45.23,36.44 45.17,36.39 | v24.85,34.77 27.29,37.41 27.5,37.82 32.68,37.82 33.08,38.22 35.73,38.22 36.94,37 39.38,37 40.2,36.19 45.07,36.19 45.28,36.39 45.23,36.44
PD0
  Top 0.203: MCU2.25 63.1,17.54 57.16,11.6 53.71,11.6 47.61,6.73 47.61,5.51 47.41,5.3 47.56,5.15 JP3.15
PD1
  Top 0.203: MCU2.26 63.9,17.32 57.57,10.99 54.12,10.99 48.83,6.52 48.83,3.88 47.46,2.51 | 47.46,2.51 47.41,2.46 | JP3.16 47.46,2.51
PD2
  Top 0.203: MCU2.27 64.7,17.31 57.98,10.59 55.33,10.59 50.25,6.12 50.25,4.9 JP3.13
PD3
  Top 0.203: MCU2.28 65.5,17.3 58.18,9.98 55.74,9.98 51.47,6.12 51.47,4.08 50.05,2.66 50.1,2.61 JP3.14
PD4
  Top 0.203: MCU2.29 66.3,17.29 58.38,9.37 56.15,9.37 52.69,6.12 52.69,5.1 JP3.11
PD5
  Top 0.203: MCU2.30 67.1,17.27 58.59,8.76 56.35,8.76 53.91,6.32 53.91,3.88 52.54,2.51 | 52.54,2.51 52.49,2.46 | JP3.12 52.54,2.51
PD6
  Top 0.203: MCU2.31 67.9,16.85 59.2,8.15 56.55,8.15 55.74,7.34 55.74,5.51 55.54,5.51 55.13,5.1 JP3.9
PD7
  Top 0.203: MCU2.32 68.7,16.43 59.6,7.34 56.96,7.34 56.55,6.93 56.55,3.68 55.18,2.31 | 55.18,2.31 55.13,2.26 | 55.18,2.31 JP3.10
PF0
  Top 0.203: MCU2.61 59.2,36.19 59.2,38.63 60.01,39.44 69.36,39.44 72.81,35.99 72.81,13.64 66.51,7.34 66.51,3.88 65.7,3.07 JP3.2
PF1
  Top 0.203: MCU2.60 59.8,36.19 59.8,38.63 60.21,39.04 69.15,39.04 72.4,35.78 72.4,16.68 65.7,9.98 65.7,5.71 JP3.1
PF2  (via drill 0.51)
  Top 0.203: MCU2.59 60.7,35.87 60.82,35.99 60.82,36.6 60.41,37 60.62,38.02 v60.62,38.22
  Bottom 0.203: v60.62,38.22 61.63,39.24 70.17,39.24 72.81,36.6 72.81,8.76 70.17,6.12 67.93,6.12 65.49,3.68 64.28,3.68 63.46,2.87 JP3.4
PF3  (via drill 0.51)
  Top 0.203: MCU2.58 61.43,35.78 v61.43,37.21
  Bottom 0.203: v61.43,37.21 61.43,38.43 61.84,38.83 69.96,38.83 72.4,36.39 72.4,8.96 70.17,6.73 63.87,6.73 62.85,5.71 JP3.3
PF4  (via drill 0.51)
  Top 0.203: MCU2.57 62.3,35.73 62.24,35.78 v62.24,38.02
  Bottom 0.203: v62.24,38.02 64.68,38.02 65.09,38.43 69.76,38.43 72,36.19 72,9.16 69.96,7.13 63.26,7.13 61.43,5.3 61.43,3.88 60.62,3.07 JP3.6 59.7,2.05 59.7,1.24 29.83,1.24 29.83,1.65 24.14,1.65 23.74,2.05 23.74,6.73 18.25,12.21 18.25,15.87 19.27,16.89 19.27,19.93 20.08,19.93 21.5,21.36 21.5,25.22 21.91,25.22 22.31,25.62 22.31,28.67 22.52,28.67 22.52,28.88 22.72,28.88 22.72,29.69 23.13,29.69 23.94,30.5 23.94,35.17 24.14,35.17 24.14,35.99 24.35,35.99 27.6,39.24 36.54,39.24 36.74,39.04 36.74,37.82 36.94,37.82 36.94,37.61 37.15,37.61 37.15,37.41 38.77,37.41 38.77,37.82 44.06,43.1 50.56,43.1 JP6.1
PF5  (via drill 0.51)
  Top 0.203: 63.06,35.99 63.1,35.94 MCU2.56 63.06,36.19 63.06,37.61 63.67,38.22 69.36,38.22 72,35.58 72,17.09 60.62,5.71 JP3.5 | v38.57,46.35 40.4,46.35 41.82,44.93 53.81,44.93 55.03,43.71 55.64,43.71 JP6.5 | v6.06,5.3 12.76,5.3 13.98,4.08 13.98,1.85 14.59,1.24 29.83,1.24 v30.64,2.05
  Bottom 0.203: v38.57,46.35 38.16,46.76 38.16,47.16 11.75,47.16 11.75,40.05 13.17,38.63 13.17,29.69 6.06,22.58 v6.06,5.3 | v30.64,2.05 38.98,2.05 41.21,4.29 41.21,6.12 41.62,6.52 58.48,6.52 59.09,5.91 59.91,5.91 59.91,5.71 JP3.5
PF6  (via drill 0.51)
  Top 0.203: MCU2.55 63.9,36.16 63.87,36.39 v63.87,37.21 | v71.18,10.79 71.18,7.74 67.73,4.29 67.73,3.07 66.1,1.44 59.2,1.44 58.38,2.26 JP3.8
  Bottom 0.203: v71.18,10.79 71.39,10.99 71.39,36.19 69.56,38.02 65.29,38.02 64.48,37.21 v63.87,37.21 63.77,36.8 63.77,36.6 62.75,36.6 62.55,36.39 60.11,36.39 54.42,42.08 54.42,43.1 JP6.3
PF7  (via drill 0.51)
  Top 0.203: MCU2.54 64.68,36.19 64.68,37.41 65.09,37.82 69.15,37.82 71.59,35.38 71.59,18.51 58.38,5.3 JP3.7 58.08,4.49 56.66,3.07 56.66,2.46 55.64,1.44 32.47,1.44 29.22,4.69 v22.52,4.69 | v36.94,42.08 37.55,41.47 55.84,41.47 57.47,43.1 57.47,43.71 58.28,44.52 59.3,44.52 60.11,43.71 60.72,43.71 JP6.9 | v29.02,41.88 v35.32,41.88 | v23.33,38.43 20.89,38.43 18.25,35.78 18.25,31.92 17.84,31.52 15.61,31.52 v15.4,31.72 | v17.84,9.77 17.84,8.35 20.08,6.12 22.31,6.12 v22.52,6.32
  Bottom 0.203: v36.94,42.08 36.74,41.88 v35.32,41.88 | v29.02,41.88 25.57,38.43 v23.33,38.43 | v15.4,31.72 15.81,31.72 15.81,19.12 17.84,17.09 v17.84,9.77 | v22.52,4.69 v22.52,6.32
R1OUT
  Top 0.203: R3.2 15.2,19.53 16.83,21.15 17.44,21.15 17.64,21.36 17.64,25.01 17.23,25.42 RS232.12
R2IN  (via drill 0.51)
  Top 0.203: v11.34,20.75 10.53,21.56 RS232.8
  Bottom 0.203: v11.34,20.75 11.34,6.52 12.36,5.51 12.36,4.49 JP1.3
R2OUT  (via drill 0.51)
  Top 0.203: v10.53,7.95 12.36,9.77 12.36,18.11 15.4,21.15 15.4,21.56 RS232.9
  Bottom 0.203: v10.53,7.95 10.53,4.29 JP1.2
RS232-RX  (via drill 0.51)
  Top 0.203: v17.84,19.32 18.05,19.53 18.05,25.83 17.23,26.64 RS232.13
  Bottom 0.203: v17.84,19.32 18.05,19.32 21.09,22.37 21.09,28.06 22.31,29.28 22.31,39.64 24.35,41.68 26.58,41.68 26.99,42.08 26.99,43.1 JP5.3
RS232-TX  (via drill 0.51)
  Top 0.203: v14.59,28.27 15.4,28.27 RS232.14 | v14.59,32.53 14.59,33.75 23.94,43.1 24.55,43.1 JP5.2
  Bottom 0.203: v14.59,28.27 v14.59,32.53
RST#  (via drill 0.51)
  Top 0.203: v52.29,13.23 56.76,17.7 57.37,17.7 58.99,19.32 58.99,19.53 MCU2.20 | 38.57,10.18 31.76,10.18 v29.93,12.01 | 38.57,10.18 38.67,10.18 | v20.99,14.45 20.59,14.85 20.38,14.85 19.37,15.87 19.37,18.31 18.76,18.92 18.76,27.66 | 18.76,27.66 18.76,28.88 19.16,29.28 MCU1.4 | 18.76,27.66 v17.95,27.66 | v14.39,35.38 14.39,42.9 13.58,43.71 13.58,44.12 JP2.2 | v55.23,42.49 54.42,42.49 54.22,42.29 v38.57,42.29 | 38.57,10.18 39.99,11.6 v40.04,12.01
  Bottom 0.203: v52.29,13.23 51.47,13.23 50.25,12.01 v40.04,12.01 | v29.93,12.01 29.12,12.82 23.02,12.82 21.4,14.45 v20.99,14.45 | v14.39,35.38 14.39,34.56 16.22,32.74 16.22,28.27 17.84,28.27 17.84,28.06 v17.95,27.66 | v55.23,42.49 55.23,44.32 55.64,44.32 55.64,45.74 JP6.6 | v38.57,42.29 37.35,41.07 33.9,41.07 28.41,46.55 12.97,46.55 12.76,46.35 12.76,45.33 JP2.2
SCK
  Top 0.203: JP2.4 16.42,45.33 17.23,45.33 18.45,46.55 35.73,46.55 36.94,45.33 JP4.2
T2IN  (via drill 0.51)
  Top 0.203: v9.31,7.95 11.95,10.59 11.95,19.53 15.4,22.98 RS232.10
  Bottom 0.203: v9.31,7.95 7.07,5.71 7.07,4.49 JP1.1
T2OUT  (via drill 0.51)
  Top 0.203: v11.54,21.97 10.53,22.98 RS232.7
  Bottom 0.203: v11.54,21.97 15.2,18.31 15.2,4.49 JP1.4
VCC  (via drill 0.51)
  Top 0.203: 58.99,18.11 58.18,17.29 57.16,17.29 57.16,15.67 C9.1 56.53,16.03 | 58.99,18.11 59.9,19.01 | 56.55,16.07 56.52,16.04 56.53,16.03 | 58.99,18.11 v60.21,18.11 | v33.59,37 33.59,28.47 | 49.75,27.45 49.85,27.45 49.85,15.26 | 49.75,27.45 48.83,27.45 RAM.33 | 49.85,15.26 49.85,14.24 50.05,14.04 50.05,12.62 50.46,12.21 55.13,12.21 55.13,14.65 56.55,16.07 | 56.55,16.07 56.53,16.03 | 45.28,15.26 33.8,15.26 33.8,19.05 29.32,19.05 | 45.28,15.26 49.85,15.26 | C5.+ 9.61,15.87 | 22.62,28.88 22.42,28.67 v22.42,24 | 22.62,28.88 26.28,32.53 26.28,32.74 MCU1.38 | v21.4,30.09 22.62,28.88 | 55.99,34.92 57.98,32.94 57.98,25.83 60.01,23.8 60.01,21.36 | 55.99,34.92 55.94,34.97 | C14.2 13.68,32.33 15.3,30.7 RS232.16 17.23,30.91 | 12.46,20.75 12.46,31.92 12.51,31.97 | 12.51,31.97 12.87,32.33 C14.2 | C14.2 13.68,33.14 | 29.32,19.05 29.32,16.07 28.11,16.07 26.89,14.85 26.89,13.03 X1.1 26.58,12.42 24.96,12.42 X1.4 | v29.32,19.73 29.32,19.05 | JP2.5 18.05,41.68 18.05,37.82 13.37,33.14 C14.2 | C5.+ 8.9,15.67 | C5.+ 10.94,16.68 10.94,19.12 12.36,20.54 12.36,31.72 12.56,31.92 12.51,31.97 | 6.87,15.46 IC4.4 6.87,15.06 8.9,15.06 C5.+ | JP6.7 59.3,42.9 55.84,39.44 L1.1 55.84,38.63 55.84,35.17 56.05,34.97 55.99,34.92 | v57.47,44.93 55.84,44.93 55.03,45.74 54.42,45.74 JP6.4 | 49.75,27.45 49.75,28.88 C7.1 | 45.28,15.26 v40.4,10.38
  Top 0.254: MCU2.52 66.3,36.39 66.71,36.8 69.36,36.8 69.76,36.39 v69.76,35.78 | MCU1.38 26.42,33.69 26.48,33.75 26.28,33.96 v26.28,34.97 | v61.23,22.17 60.82,22.17 60.01,21.36 60.01,20.34 59.8,20.14 | 59.8,20.14 59.83,20.11 MCU2.21 | 59.9,19.01 59.9,20.04 59.8,20.14 | RAM.11 37.01,28.43 37.05,28.47 33.59,28.47
  Bottom 0.203: IC1.4 66.46,17.55 66.1,18.11 62.85,18.11 62.45,18.51 60.82,18.51 v60.21,18.11 | IC1.14 62.45,9.57 60.62,9.57 C10.1 59.7,8.96 54.01,8.96 52.59,7.54 42.43,7.54 39.99,9.98 | v29.32,19.73 27.9,19.73 24.04,23.59 C6.2 v22.42,24 | v21.4,30.09 21.3,30.5 21.3,34.36 19.06,36.6 19.06,41.88 JP2.5 | v57.47,44.93 57.87,44.52 57.87,43.91 58.28,43.91 JP6.7 | v40.4,10.38 39.99,9.98 | 39.99,9.98 39.38,9.37 38.98,9.37 38.98,8.35 J1.3
  Bottom 0.254: v69.76,35.78 69.76,21.15 61.43,21.15 v61.23,22.17 | v33.59,37 27.9,37 26.28,35.58 v26.28,34.97
  Bottom 0.406: C6.2 23.84,24
VCC-LCD  (via drill 0.51)
  Top 0.203: IC3.4 15.3,15.67 16.93,15.67 C4.+ 18.86,15.06 20.69,13.23 v21.3,13.23
  Bottom 0.203: 31.01,7.8 J1.19 30.79,7.82 | 30.79,7.82 30.87,7.82 30.95,7.74 | 30.79,7.82 J1.20 | 30.77,7.83 30.79,7.82 | 30.67,9.24 30.64,9.24 30.64,9.16 | 30.64,9.16 30.64,10.18 30.04,10.79 23.74,10.79 v21.3,13.23 | 30.64,9.16 30.75,9
  Bottom 0.406: 30.75,9 30.77,7.83
VS+
  Top 0.203: IC3.1 13.27,13.64 13.27,15.06 IC3.6 | IC3.1 13.47,12.62 | 4.74,14.45 IC4.6 | IC4.1 4.74,13.03 | 3.11,11.6 C1.+ | IC3.1 13.27,12.62 | IC4.6 4.74,15.46 | IC4.6 4.64,15.46 | 8.29,36.8 J2.PWR | 4.13,33.6 4.23,33.75
  Top 0.305: 12.97,7.54 15,5.51 35.52,5.51 36.13,4.9
  Top 0.406: 4.74,13.03 4.74,14.45 | 4.64,15.46 4.64,18.51 4.13,19.63 4.13,33.6 | 8.29,36.8 7.28,36.8 4.23,33.75 | 3.11,10.59 3.11,7.44 4.23,6.32 11.75,6.32 12.97,7.54 12.97,12.82 13.19,13.05 IC3.1 | 3.11,10.59 3.11,11.6 | 3.11,10.59 3.21,10.59 4.75,12.13 IC4.1 | 36.13,4.9 SJ1.1
WE#  (via drill 0.51)
  Top 0.203: RAM.17 36.01,23.61 35.83,23.8 35.83,24.61 34.86,25.57 | 34.86,25.57 34.81,25.62 | 49.14,39.19 34.71,39.19 34.71,39.24 32.68,37.21 32.68,36.6 32.88,36.39 32.88,25.62 34.91,25.62 34.86,25.57 | 49.14,39.19 49.24,39.19 | v52.87,38.65 53.2,37.21 53.2,31.72 54.01,30.91 54.42,30.91 MCU2.5 | v49.75,38.63 49.14,39.24 49.14,39.19
  Top 0.229: RAM.17 36.44,23.59
  Bottom 0.203: v52.87,38.65 52.59,38.63 v49.75,38.63

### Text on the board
tNames: 1 | 1 | 1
